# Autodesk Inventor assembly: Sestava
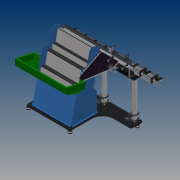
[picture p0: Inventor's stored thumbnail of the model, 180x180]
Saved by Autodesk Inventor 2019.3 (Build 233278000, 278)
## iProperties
Created: 2019-02
Part Number: Sestava
Material: Všeobecné
Document SubType Name: Assembly
Designer: B-hon
Mass: 359871 g
Surface Area: 168702 cm^2
Volume: 49988.6 cm^3
Density: 7.19907 g/cm^3
Stock Number: 19-A0-S-23
Author: B-hon
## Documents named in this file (99)
- C:\Users\B-hon\OneDrive\Plocha\Bakalářka22\Sestava.iam
- C:\Users\B-hon\OneDrive\Plocha\Bakalářka22\Rám\Rám.iam
- C:\Users\B-hon\OneDrive\Plocha\Bakalářka22\Vodící lišta.ipt
- C:\Users\B-hon\OneDrive\Plocha\Bakalářka22\Vozík.ipt
- C:\Users\B-hon\OneDrive\Plocha\Bakalářka22\Výztuha rohu-P.ipt
- C:\Users\B-hon\OneDrive\Plocha\Bakalářka22\Výztuha rohu-L.ipt
- C:\Users\B-hon\OneDrive\Plocha\Bakalářka22\Přítlak spodní\Pravý\Přítlak4s.iam
- C:\Users\B-hon\OneDrive\Plocha\Bakalářka22\Přítlak spodní\Levý\Přítlak3s.iam
- C:\Users\B-hon\OneDrive\Plocha\Bakalářka22\Deska horní\Deska1.iam
- C:\Users\B-hon\OneDrive\Plocha\Bakalářka22\Deska pevná\Deska pevná.iam
- C:\Users\B-hon\OneDrive\Plocha\Bakalářka22\Deska dolní\Deska dolní.iam
- C:\Users\B-hon\OneDrive\Plocha\Bakalářka22\Deska dolní\Ramano pravé.iam
- C:\Users\B-hon\OneDrive\Plocha\Bakalářka22\Deska dolní\Ramano levé.iam
- C:\Users\B-hon\OneDrive\Plocha\Bakalářka22\Deska střední\Deska střední.iam
- C:\Users\B-hon\OneDrive\Plocha\Bakalářka22\Deska střední\Držák desky.ipt
- C:\Users\B-hon\OneDrive\Plocha\Bakalářka22\Přítlak\Střední\Přítlak5.iam
- C:\Users\B-hon\OneDrive\Plocha\Bakalářka22\Deska střední\Rameno pravés.iam
- C:\Users\B-hon\OneDrive\Plocha\Bakalářka22\Deska střední\Rameno levés.iam
- C:\Users\B-hon\OneDrive\Plocha\Bakalářka22\Držák převodovky.ipt
- C:\Users\B-hon\OneDrive\Plocha\Bakalářka22\Převodovka.ipt
- C:\Users\B-hon\OneDrive\Plocha\Bakalářka22\Klika\Klika.iam
- C:\Users\B-hon\OneDrive\Documents\Inventor\Content Center Files\R2019\cs-CZ\CSN 02 2930\CSN 02 2930 - 25.ipt
- C:\Users\B-hon\OneDrive\Plocha\Bakalářka22\Ojnice\Ojnice.iam
- C:\Users\B-hon\OneDrive\Documents\Inventor\Content Center Files\R2019\cs-CZ\DIN 988(2)\DIN 988 - 12 x 18 x 1,8.ipt
- C:\Users\B-hon\OneDrive\Plocha\Bakalářka22\Rozpěrná tyčka\Držák dolní.ipt
- C:\Users\B-hon\OneDrive\Plocha\Bakalářka22\Rozpěrná tyčka\Držák horní.ipt
- C:\Users\B-hon\OneDrive\Plocha\Bakalářka22\Rozpěrná tyčka\Tyčka.ipt
- C:\Users\B-hon\OneDrive\Documents\Inventor\Content Center Files\R2019\cs-CZ\CSN EN 24032\ISO 4032 - M10CSN EN.ipt
- C:\Users\B-hon\OneDrive\Documents\Inventor\Content Center Files\R2019\cs-CZ\CSN EN 24034\ISO 4034 - M10CSN EN.ipt
- C:\Users\B-hon\OneDrive\Plocha\Bakalářka22\Motor.ipt
- C:\Users\B-hon\OneDrive\Plocha\Bakalářka22\Základ2.ipt
- C:\Users\B-hon\OneDrive\Plocha\Bakalářka22\Boční plech.ipt
- C:\Users\B-hon\OneDrive\Plocha\Bakalářka22\Boční plech2.ipt
- C:\Users\B-hon\OneDrive\Plocha\Bakalářka22\Plech přední.ipt
- C:\Users\B-hon\OneDrive\Plocha\Bakalářka22\Plech násypky3.ipt
- C:\Users\B-hon\OneDrive\Plocha\Bakalářka22\Plech násypky1.ipt
- C:\Users\B-hon\OneDrive\Plocha\Bakalářka22\Plech násypky2.ipt
- C:\Users\B-hon\OneDrive\Plocha\Bakalářka22\Plech násypky2-L.ipt
- C:\Users\B-hon\OneDrive\Plocha\Bakalářka22\Plech násypky3-L.ipt
- C:\Users\B-hon\OneDrive\Plocha\Bakalářka22\Plech zadní.ipt
- C:\Users\B-hon\OneDrive\Plocha\Bakalářka22\Držák sloupu.iam
- C:\Users\B-hon\OneDrive\Plocha\Bakalářka22\Úchyt sloupu2.ipt
- C:\Users\B-hon\OneDrive\Plocha\Bakalářka22\Přítlak\Pravý\Přítlak1h.iam
- C:\Users\B-hon\OneDrive\Plocha\Bakalářka22\Přítlak\Levý\Přítlak2h.iam
- C:\Users\B-hon\OneDrive\Plocha\Bakalářka22\Vibrační dopravník3\Dopravník vibrační3.iam
- C:\Users\B-hon\OneDrive\Plocha\Bakalářka22\Skluzová dráha2.ipt
- C:\Users\B-hon\OneDrive\Plocha\Bakalářka22\Držák dráhy.iam
- C:\Users\B-hon\OneDrive\Plocha\Bakalářka22\Držák dráhy2.iam
- C:\Users\B-hon\OneDrive\Plocha\Bakalářka22\Zadní plech krycí.ipt
- C:\Users\B-hon\OneDrive\Documents\Inventor\Content Center Files\R2019\cs-CZ\CNS 4558\CNS 4558 - M4 x 0,7 x 16.ipt
- C:\Users\B-hon\OneDrive\Documents\Inventor\Content Center Files\R2019\cs-CZ\DIN 125-2  A\DIN 125-2 - B 10,5A.ipt
- C:\Users\B-hon\OneDrive\Documents\Inventor\Content Center Files\R2019\cs-CZ\DIN 933\DIN 933 - M10  x 45.ipt
- C:\Users\B-hon\OneDrive\Plocha\Bakalářka22\Antivibrační noha.ipt
- C:\Users\B-hon\OneDrive\Documents\Inventor\Content Center Files\R2019\cs-CZ\ANSI B18.6.4(280)\ANSI B18.6.4 - 1_4-14 - 0,75(22) BP.ipt
- C:\Users\B-hon\OneDrive\Plocha\Bakalářka22\Matice upínací.ipt
- C:\Users\B-hon\OneDrive\Documents\Inventor\Content Center Files\R2019\cs-CZ\DIN 125-1  A\DIN 125 - A 6,4.ipt
- C:\Users\B-hon\OneDrive\Documents\Inventor\Content Center Files\R2019\cs-CZ\DIN 933\DIN 933 - M6  x 45.ipt
- C:\Users\B-hon\OneDrive\Documents\Inventor\Content Center Files\R2019\cs-CZ\DIN 933\DIN 933 - M6  x 35.ipt
- C:\Users\B-hon\OneDrive\Documents\Inventor\Content Center Files\R2019\cs-CZ\DIN 933\DIN 933 - M6  x 6.ipt
- C:\Users\B-hon\OneDrive\Documents\Inventor\Content Center Files\R2019\cs-CZ\ANSI B18.6.4(324)\ANSI B18.6.4 - 1_4-14 - 0,75(26) BP.ipt
- C:\Users\B-hon\OneDrive\Documents\Inventor\Content Center Files\R2019\cs-CZ\DIN 933\DIN 933 - M6  x 16.ipt
- C:\Users\B-hon\OneDrive\Documents\Inventor\Content Center Files\R2019\cs-CZ\CSN EN 24034\ISO 4034 - M6CSN EN.ipt
- C:\Users\B-hon\OneDrive\Documents\Inventor\Content Center Files\R2019\cs-CZ\DIN 7991(2)\DIN 7991 - M4x10.ipt
- C:\Users\B-hon\OneDrive\Plocha\Bakalářka22\Vibrační dopravník3\Základová deska3.ipt
- C:\Users\B-hon\OneDrive\Plocha\Bakalářka22\Příruba.ipt
- C:\Users\B-hon\OneDrive\Plocha\Bakalářka22\Nosný sloup.ipt
- C:\Users\B-hon\OneDrive\Plocha\Bakalářka22\Držák tyče.ipt
- C:\Users\B-hon\OneDrive\Plocha\Bakalářka22\Elektromagnet.ipt
- C:\Users\B-hon\OneDrive\Plocha\Bakalářka22\Tyčka elektromotoru.ipt
- C:\Users\B-hon\OneDrive\Plocha\Bakalářka22\Tyč válce.ipt
- C:\Users\B-hon\OneDrive\Plocha\Bakalářka22\Držák elektromagnetu.ipt
- C:\Users\B-hon\OneDrive\Plocha\Bakalářka22\Zarážka.ipt
- C:\Users\B-hon\OneDrive\Plocha\Bakalářka22\Držák elektromagnetu2.ipt
- C:\Users\B-hon\OneDrive\Documents\Inventor\Content Center Files\R2019\cs-CZ\DIN 933\DIN 933 - M6  x 25.ipt
- C:\Users\B-hon\OneDrive\Documents\Inventor\Content Center Files\R2019\cs-CZ\CNS 4558\CNS 4558 - M6 x 1 x 8.ipt
- C:\Users\B-hon\OneDrive\Documents\Inventor\Content Center Files\R2019\cs-CZ\DIN 125-1  A\DIN 125 - A 4,3.ipt
- C:\Users\B-hon\OneDrive\Documents\Inventor\Content Center Files\R2019\cs-CZ\DIN 933\DIN 933 - M4  x 5.ipt
- C:\Users\B-hon\OneDrive\Plocha\Bakalářka22\Senzor.ipt
- C:\Users\B-hon\OneDrive\Plocha\Bakalářka22\Držák senzoru2.ipt
- C:\Users\B-hon\OneDrive\Plocha\Bakalářka22\Držák senzoru3.ipt
- C:\Users\B-hon\OneDrive\Documents\Inventor\Content Center Files\R2019\cs-CZ\DIN 933\DIN 933 - M6  x 20.ipt
- C:\Users\B-hon\OneDrive\Documents\Inventor\Content Center Files\R2019\cs-CZ\ISO 4035(1)\ISO 4035 - M18DIN EN.ipt
- C:\Users\B-hon\OneDrive\Documents\Inventor\Content Center Files\R2019\cs-CZ\DIN 125-1  A\DIN 125 - A 10,5.ipt
- C:\Users\B-hon\OneDrive\Documents\Inventor\Content Center Files\R2019\cs-CZ\CNS 3932\CNS 3932 - M 6 x 1 x 10.ipt
- C:\Users\B-hon\OneDrive\Documents\Inventor\Content Center Files\R2019\cs-CZ\DIN 933\DIN 933 - M10  x 8.ipt
- C:\Users\B-hon\OneDrive\Documents\Inventor\Content Center Files\R2019\cs-CZ\DIN 125-1  A\DIN 125 - A 15.ipt
- C:\Users\B-hon\OneDrive\Documents\Inventor\Content Center Files\R2019\cs-CZ\CSN EN 24034\ISO 4034 - M14CSN EN.ipt
- C:\Users\B-hon\OneDrive\Documents\Inventor\Content Center Files\R2019\cs-CZ\DIN 933\DIN 933 - M14  x 35.ipt
- C:\Users\B-hon\OneDrive\Documents\Inventor\Content Center Files\R2019\cs-CZ\CSN EN 24034\ISO 4034 - M5CSN EN.ipt
- C:\Users\B-hon\OneDrive\Documents\Inventor\Content Center Files\R2019\cs-CZ\CNS 4558\CNS 4558 - M4 x 0,7 x 10.ipt
- C:\Users\B-hon\OneDrive\Documents\Inventor\Content Center Files\R2019\cs-CZ\DIN 125-1  A\DIN 125 - A 8,4.ipt
- C:\Users\B-hon\OneDrive\Documents\Inventor\Content Center Files\R2019\cs-CZ\CSN EN 24034\ISO 4034 - M8CSN EN.ipt
- C:\Users\B-hon\OneDrive\Documents\Inventor\Content Center Files\R2019\cs-CZ\DIN 933\DIN 933 - M8  x 25.ipt
- C:\Users\B-hon\OneDrive\Documents\Inventor\Content Center Files\R2019\cs-CZ\DIN 933\DIN 933 - M8  x 8.ipt
- C:\Users\B-hon\OneDrive\Documents\Inventor\Content Center Files\R2019\cs-CZ\CNS 4558\CNS 4558 - M4 x 0,7 x 8.ipt
- C:\Users\B-hon\OneDrive\Documents\Inventor\Content Center Files\R2019\cs-CZ\IFI 502(29)\IFI 502 - 6.3x1.8 x 13(4) B.ipt
- C:\Users\B-hon\OneDrive\Plocha\Bakalářka22\Zátka sloupu.ipt
- C:\Users\B-hon\OneDrive\Documents\Inventor\Content Center Files\R2019\cs-CZ\DIN 933\DIN 933 - M12  x 30.ipt
- C:\Users\B-hon\OneDrive\Documents\Inventor\Content Center Files\R2019\cs-CZ\CSN 02 1143  A\CSN 02 1143 - M6 x 1 x 10(1).ipt
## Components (426 placed, 98 different names)
1. Rám:1 [sub-assembly] — Vložit:3, Vložit:4, Vložit:5, Vložit:6, Proti sobě:12, Stejný směr:12, Proti sobě:13, Stejný směr:13, Stejný směr:15, Vložit:76, Vložit:77, Vložit:78, Vložit:79, Proti sobě:26, Stejný směr:19, Proti sobě:29, Stejný směr:20, Proti sobě:67
2. Výztuha rohu-P:1 — Vložit:3, Vložit:4, Stejný směr:18, Proti sobě:286
3. Výztuha rohu-L:1 — Vložit:5, Vložit:6, Proti sobě:23
4. Držák desky:1 — Proti sobě:12, Stejný směr:12, Stejný směr:14, Vložit:90, Vložit:91
5. Držák desky:2 — Proti sobě:13, Stejný směr:13, Stejný směr:14, Stejný směr:15, Vložit:92, Vložit:93
6. Rameno pravés:1 [sub-assembly] — Vložit:65, Vložit:84, Vložit:85, Vložit:86
7. Rameno levés:1 [sub-assembly] — Vložit:64, Vložit:87, Vložit:88, Vložit:89
8. Držák převodovky:1 — Vložit:38, Vložit:39, Proti sobě:24, Stejný směr:18
9. Převodovka:1 — Vložit:38, Vložit:39, Vložit:40, Vložit:60, Vložit:61
10. Klika:1 [sub-assembly] — Vložit:40, Vložit:41, Vložit:42, Vložit:46
11. CSN 02 2930 25:1 — Vložit:41
12. CSN 02 2930 25:2 — Vložit:42
13. Ojnice:1 [sub-assembly] — Vložit:47, Proti sobě:25, Vložit:80
14. DIN 988 12 x 18 x 1,8:1 — Vložit:44, Vložit:45
15. DIN 988 12 x 18 x 1,8:2 — Vložit:44, Vložit:47
16. DIN 988 12 x 18 x 1,8:3 — Vložit:45, Vložit:46
17. Držák dolní:1 — Vložit:52, Proti sobě:16, Vložit:110, Vložit:111
18. Držák horní:1 — Vložit:117, Vložit:118
19. Tyčka:1 — Vložit:52
20. CSN EN 24032 M10:1
21. CSN EN 24032 M10:2 — Proti sobě:16
22. CSN EN 24032 M10:3
23. Držák dolní:2 — Vložit:57, Proti sobě:18, Vložit:112, Vložit:113
24. Tyčka:2 — Vložit:57
25. CSN EN 24034 M10:1 — Proti sobě:18
26. CSN EN 24034 M10:2 — Vložit:124
27. CSN EN 24034 M10:3 — Vložit:125
28. Motor:1 — Vložit:60, Vložit:61
29. Základ2:1 — Proti sobě:23, Proti sobě:24, Proti sobě:30, Proti sobě:37, Proti sobě:41, Úhel:1, Stejný směr:33, Stejný směr:34, Úhel:2, Úhel:3, Vložit:142, Vložit:143, Vložit:144, Vložit:145, Stejný směr:42, Úhel:22, Proti sobě:230, Proti sobě:232, Proti sobě:234, Proti sobě:236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
30. Deska dolní:1 [sub-assembly] — Stejný směr:17, Proti sobě:35, Stejný směr:35, Vložit:102, Vložit:103, Vložit:108, Vložit:109
31. Deska střední:1 [sub-assembly] — Vložit:64, Vložit:65, Vložit:86, Vložit:89, Stejný směr:35, Úhel:12
32. Držák horní:3 — Vložit:122, Vložit:123, Vložit:124, Vložit:125
33. Deska pevná:1 [sub-assembly] — Vložit:78, Vložit:79, Stejný směr:36, Proti sobě:50, Proti sobě:51, Proti sobě:68
34. Boční plech:1 — Proti sobě:26, Stejný směr:19, Proti sobě:32, Stejný směr:22, Proti sobě:34, Stejný směr:39, Proti sobě:89, Proti sobě:139, Proti sobě:141, Proti sobě:163
35. Boční plech2:1 — Proti sobě:29, Stejný směr:20, Proti sobě:31, Stejný směr:21, Proti sobě:36, Stejný směr:28, Proti sobě:38, Stejný směr:32, Stejný směr:33, Stejný směr:41, Vložit:221, Proti sobě:266
36. Plech přední:1 — Proti sobě:30, Proti sobě:31, Stejný směr:21, Proti sobě:33, Stejný směr:34
37. Plech násypky3:1 — Proti sobě:32, Stejný směr:22, Stejný směr:23, Proti sobě:63, Proti sobě:167
38. Plech násypky1:1 — Proti sobě:33, Stejný směr:23, Proti sobě:34, Proti sobě:35, Stejný směr:24, Stejný směr:25, Stejný směr:26, Stejný směr:27, Stejný směr:29, Stejný směr:30, Stejný směr:31
39. Plech násypky2:1 — Stejný směr:24, Stejný směr:25, Stejný směr:26
40. Plech násypky2-L:1 — Stejný směr:27, Stejný směr:30, Stejný směr:31
41. Plech násypky3-L:1 — Proti sobě:36, Stejný směr:28, Stejný směr:29, Proti sobě:165
42. Plech zadní:1 — Proti sobě:37, Proti sobě:38, Stejný směr:32
43. Přítlak5:1 [sub-assembly] — Vložit:84, Vložit:85, Vložit:90, Vložit:91
44. Přítlak5:2 [sub-assembly] — Vložit:87, Vložit:88, Vložit:92, Vložit:93
45. Přítlak4s:1 [sub-assembly] — Vložit:104, Vložit:105, Vložit:106, Vložit:107, Vložit:110, Vložit:111
46. Přítlak3s:1 [sub-assembly] — Vložit:96, Vložit:97, Vložit:100, Vložit:101, Vložit:112, Vložit:113
47. Ramano levé:1 [sub-assembly] — Vložit:104, Vložit:105, Vložit:108, Vložit:109
48. Ramano pravé:1 [sub-assembly] — Vložit:96, Vložit:97, Vložit:102, Vložit:103
49. Přítlak1h:1 [sub-assembly] — Vložit:114, Vložit:115, Proti sobě:47, Vložit:117, Vložit:118
50. Přítlak2h:1 [sub-assembly] — Vložit:119, Proti sobě:48, Vložit:122, Vložit:123, Vložit:180
51. Dopravník vibrační3:1 [sub-assembly] — Úhel:2, Úhel:3, Stejný směr:36, Proti sobě:50, Proti sobě:51, Proti sobě:62, Proti sobě:88, Proti sobě:146, Proti sobě:147, Proti sobě:148, Proti sobě:149, Stejný směr:40, Proti sobě:150, Proti sobě:151, Proti sobě:152, Proti sobě:153, Proti sobě:155, Proti sobě:157, Proti sobě:159, Proti sobě:161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
52. Skluzová dráha2:1 — Proti sobě:62, Proti sobě:63, Proti sobě:64, Proti sobě:88, Proti sobě:89, Vložit:133, Vložit:134, Vložit:138, Vložit:139
53. Držák dráhy:1 [sub-assembly] — Proti sobě:64, Vložit:128, Vložit:133, Vložit:134, Proti sobě:272, Proti sobě:274, Proti sobě:276, Proti sobě:278
54. Držák dráhy2:1 [sub-assembly] — Vložit:128, Proti sobě:182
55. CNS 4558 M4 x 16:1 — Vložit:138
56. CNS 4558 M4 x 16:2 — Vložit:139
57. Antivibrační noha:1 — Proti sobě:129
58. Antivibrační noha:2 — Proti sobě:125
59. Antivibrační noha:3 — Proti sobě:127
60. Antivibrační noha:4 — Proti sobě:123
61. CSN EN 24034 M10:4 — Proti sobě:123, Proti sobě:131
62. CSN EN 24034 M10:5 — Proti sobě:125, Proti sobě:133
63. CSN EN 24034 M10:6 — Proti sobě:127, Proti sobě:135
64. CSN EN 24034 M10:7 — Proti sobě:129, Proti sobě:137
65. DIN 125-2 A B 10,5:17 — Proti sobě:131, Vložit:143
66. DIN 125-2 A B 10,5:18 — Proti sobě:133, Vložit:144
67. DIN 125-2 A B 10,5:19 — Proti sobě:135, Vložit:145
68. DIN 125-2 A B 10,5:20 — Proti sobě:137, Vložit:142
69. DIN 125-1 A A 6,4:1 — Proti sobě:155, Vložit:154
70. DIN 125-1 A A 6,4:2 — Proti sobě:157
71. Deska1:1 [sub-assembly] — Stejný směr:17, Proti sobě:25, Vložit:80, Proti sobě:47, Vložit:180, Úhel:12
72. Zadní plech krycí:1 — Proti sobě:67, Stejný směr:39, Proti sobě:68
73. CSN EN 24034 M6:1 — Proti sobě:169
74. CSN EN 24034 M6:2 — Proti sobě:171
75. CSN EN 24034 M6:3 — Proti sobě:173
76. CSN EN 24034 M6:4 — Proti sobě:175
77. Šroub do plechu s vroubkovanou šestihrannou hlavou s drážkou a podložkou - Typ BP - Palcový 1/4-14 - 0,75:7
78. Šroub do plechu s vroubkovanou šestihrannou hlavou s drážkou a podložkou - Typ BP - Palcový 1/4-14 - 0,75:8
79. Šroub do plechu s vroubkovanou šestihrannou hlavou s drážkou a podložkou - Typ BP - Palcový 1/4-14 - 0,75:9
80. DIN 933 - nahrazený DIN EN 24017 M6  x 6:4
81. DIN 933 - nahrazený DIN EN 24017 M6  x 6:5
82. DIN 933 - nahrazený DIN EN 24017 M6  x 6:6
83. Základová deska3:1 — Vložit:181, Vložit:183, Vložit:184, Úhel:13, Proti sobě:187, Úhel:22, Proti sobě:218, Proti sobě:223, Proti sobě:224
84. Držák tyče:1 — Proti sobě:182, Úhel:13, Proti sobě:189, Proti sobě:224, Proti sobě:260
85. Elektromagnet:1 — Úhel:15, Proti sobě:195, Úhel:16, Vložit:188, Proti sobě:197
86. Tyčka elektromotoru:1 — Vložit:187, Proti sobě:197
87. Držák tyče:2 — Proti sobě:187, Proti sobě:189, Proti sobě:190, Stejný směr:46, Stejný směr:47, Proti sobě:223, Proti sobě:262
88. Tyč válce:1 — Proti sobě:190, Proti sobě:191, Proti sobě:192, Proti sobě:193
89. Držák elektromagnetu:1 — Proti sobě:191, Proti sobě:192, Proti sobě:193, Úhel:14, Proti sobě:194, Úhel:16, Proti sobě:196, Proti sobě:205, Proti sobě:207, Stejný směr:45
90. Zarážka:1 — Vložit:187, Úhel:15, Proti sobě:199
91. Držák elektromagnetu2:1 — Vložit:188, Proti sobě:196, Proti sobě:202, Proti sobě:203, Stejný směr:45, Úhel:21, Proti sobě:217, Vložit:200, Vložit:203, Vložit:204
92. DIN 125-1 A A 6,4:31 — Proti sobě:199, Proti sobě:201
93. CSN EN 24034 M6:5 — Proti sobě:201
94. DIN 125-1 A A 6,4:32 — Proti sobě:202, Vložit:192
95. DIN 125-1 A A 6,4:33 — Proti sobě:203, Vložit:191
96. DIN 125-1 A A 6,4:34 — Proti sobě:205
97. DIN 125-1 A A 6,4:35 — Proti sobě:207
98. CSN EN 24034 M6:6 — Proti sobě:208
99. CSN EN 24034 M6:7 — Proti sobě:209
100. DIN 933 - nahrazený DIN EN 24017 M6  x 25:1 — Vložit:192, Proti sobě:208
101. DIN 933 - nahrazený DIN EN 24017 M6  x 25:2 — Vložit:191, Proti sobě:209
102. DIN 933 - nahrazený DIN EN 24017 M4  x 5:1
103. DIN 933 - nahrazený DIN EN 24017 M4  x 5:2
104. DIN 933 - nahrazený DIN EN 24017 M4  x 5:3
105. Držák tyče:3 — Proti sobě:218, Stejný směr:46, Stejný směr:47, Proti sobě:219, Proti sobě:264, Proti sobě:284
106. Tyč válce:2 — Proti sobě:219, Proti sobě:220, Proti sobě:221
107. Držák senzoru3:1 — Proti sobě:220, Proti sobě:221, Proti sobě:222, Vložit:201, Vložit:210, Vložit:211
108. DIN 125-1 A A 6,4:37 — Vložit:202, Vložit:207
109. DIN 125-1 A A 6,4:38 — Proti sobě:225, Vložit:208
110. DIN 125-1 A A 6,4:39 — Vložit:203, Vložit:206
111. DIN 125-1 A A 6,4:40 — Vložit:204, Vložit:205
112. CSN EN 24034 M6:8 — Vložit:206
113. CSN EN 24034 M6:9 — Vložit:205, Proti sobě:226
114. DIN 933 - nahrazený DIN EN 24017 M6  x 20:1 — Vložit:207
115. DIN 933 - nahrazený DIN EN 24017 M6  x 20:2 — Vložit:208, Proti sobě:226
116. DIN 933 - nahrazený DIN EN 24017 M6  x 25:3 — Vložit:215, Proti sobě:228
117. DIN 933 - nahrazený DIN EN 24017 M6  x 25:4 — Vložit:214
118. CSN EN 24034 M6:10 — Vložit:213, Proti sobě:228
119. CSN EN 24034 M6:11 — Vložit:212
120. DIN 125-1 A A 6,4:41 — Proti sobě:227, Vložit:215
121. DIN 125-1 A A 6,4:42 — Vložit:211, Vložit:213
122. DIN 125-1 A A 6,4:43 — Vložit:210, Vložit:212
123. DIN 125-1 A A 6,4:44 — Vložit:209, Vložit:214
124. DIN 125-1 A A 10,5:1 — Proti sobě:230
125. DIN 125-1 A A 10,5:2 — Proti sobě:232
126. DIN 125-1 A A 10,5:3 — Proti sobě:234
127. DIN 125-1 A A 10,5:4 — Proti sobě:236
128. DIN 125-1 A A 10,5:5 — Proti sobě:238
129. DIN 125-1 A A 10,5:6 — Proti sobě:240
130. DIN 125-1 A A 10,5:7 — Proti sobě:242
131. DIN 125-1 A A 10,5:8 — Proti sobě:244
132. DIN 125-1 A A 10,5:9 — Proti sobě:246, Proti sobě:254
133. DIN 125-1 A A 10,5:10 — Proti sobě:248
134. DIN 125-1 A A 10,5:11 — Proti sobě:250, Proti sobě:256
135. DIN 125-1 A A 10,5:12 — Proti sobě:252, Proti sobě:258
136. CNS 3932 M 6 x 10:1 — Proti sobě:260
137. CNS 3932 M 6 x 10:2 — Proti sobě:262
138. CNS 3932 M 6 x 10:3 — Proti sobě:264
139. DIN 125-1 A A 15:1 — Proti sobě:272, Vložit:223
140. DIN 125-1 A A 15:2 — Proti sobě:274, Vložit:222
141. CSN EN 24034 M14:1 — Vložit:222
142. DIN 933 - nahrazený DIN EN 24017 M14  x 35:1 — Vložit:223
143. DIN 125-1 A A 4,3:4 — Proti sobě:276, Proti sobě:282
144. DIN 125-1 A A 4,3:5 — Proti sobě:278, Proti sobě:280
145. CSN EN 24034 M5:1 — Proti sobě:280
146. CSN EN 24034 M5:2 — Proti sobě:282
147. DIN 125-1 A A 6,4:45
148. DIN 125-1 A A 6,4:46
149. DIN 125-1 A A 6,4:47
150. DIN 125-1 A A 6,4:48
151. DIN 125-1 A A 6,4:49
152. DIN 125-1 A A 6,4:50 — Proti sobě:284
153. DIN 933 - nahrazený DIN EN 24017 M6  x 6:8
154. DIN 933 - nahrazený DIN EN 24017 M6  x 6:9
155. DIN 933 - nahrazený DIN EN 24017 M6  x 6:10
156. DIN 933 - nahrazený DIN EN 24017 M6  x 6:11
157. DIN 933 - nahrazený DIN EN 24017 M6  x 6:12
158. DIN 933 - nahrazený DIN EN 24017 M6  x 6:13
159. DIN 125-1 A A 8,4:1
160. DIN 125-1 A A 8,4:2
161. DIN 125-1 A A 8,4:3
162. DIN 125-1 A A 8,4:4
163. DIN 125-1 A A 8,4:5
164. DIN 125-1 A A 8,4:6 — Proti sobě:286
165. DIN 125-1 A A 8,4:7 — Vložit:251
166. DIN 125-1 A A 8,4:8 — Vložit:252
167. DIN 125-1 A A 8,4:9
168. DIN 125-1 A A 8,4:10
169. DIN 125-1 A A 8,4:11
170. DIN 125-1 A A 8,4:12
171. CSN EN 24034 M8:1
172. CSN EN 24034 M8:2
173. CSN EN 24034 M8:3
174. CSN EN 24034 M8:4
175. DIN 933 - nahrazený DIN EN 24017 M8  x 25:1 — Vložit:251
176. DIN 933 - nahrazený DIN EN 24017 M8  x 25:2 — Vložit:252
177. DIN 933 - nahrazený DIN EN 24017 M8  x 8:1
178. DIN 933 - nahrazený DIN EN 24017 M8  x 8:2
179. DIN 933 - nahrazený DIN EN 24017 M8  x 8:3
180. DIN 933 - nahrazený DIN EN 24017 M8  x 8:4
181. DIN 933 - nahrazený DIN EN 24017 M8  x 8:5
182. DIN 933 - nahrazený DIN EN 24017 M8  x 8:6
183. CNS 4558 M4 x 8:1
184. CSN 02 1143 A M6 x 10:1
185. CSN 02 1143 A M6 x 10:2
186. CSN 02 1143 A M6 x 10:3
187. CSN 02 1143 A M6 x 10:4
188. DIN 125-1 A A 6,4:54
189. DIN 125-1 A A 6,4:55
190. DIN 125-1 A A 6,4:56 — Proti sobě:293
191. DIN 933 - nahrazený DIN EN 24017 M6  x 6:15
192. DIN 933 - nahrazený DIN EN 24017 M6  x 6:16 — Proti sobě:293
193. DIN 933 - nahrazený DIN EN 24017 M6  x 6:17
194. Vozík:1 — Proti sobě:2, Proti sobě:3, Vložit:106, Vložit:107
195. Vozík:2 — Vložit:100, Vložit:101
196. Vozík:3 — Proti sobě:5, Proti sobě:6, Vložit:114, Vložit:115
197. Vozík:4 — Vložit:119, Proti sobě:48
198. Vodící lišta:1 — Proti sobě:2, Proti sobě:3, Proti sobě:5, Proti sobě:6, Vložit:76, Vložit:77
199. Vodící lišta:2
200. Šroub do plechu s vroubkovanou šestihrannou hlavou s drážkou a podložkou - Typ BP - Palcový 1/4-14 - 0,75:1 — Proti sobě:139
201. Šroub do plechu s vroubkovanou šestihrannou hlavou s drážkou a podložkou - Typ BP - Palcový 1/4-14 - 0,75:2
202. Šroub do plechu s vroubkovanou šestihrannou hlavou s drážkou a podložkou - Typ BP - Palcový 1/4-14 - 0,75:3
203. Šroub do plechu s vroubkovanou šestihrannou hlavou s drážkou a podložkou - Typ BP - Palcový 1/4-14 - 0,75:4 — Proti sobě:141
204. Šroub do plechu s vroubkovanou šestihrannou hlavou s drážkou a podložkou - Typ BP - Palcový 1/4-14 - 0,75:5
205. Šroub do plechu s vroubkovanou šestihrannou hlavou s drážkou a podložkou - Typ BP - Palcový 1/4-14 - 0,75:6
206. Matice upínací:1 — Proti sobě:146, Proti sobě:147, Stejný směr:40
207. Matice upínací:3
208. Matice upínací:4
209. Matice upínací:5
210. Matice upínací:2 — Proti sobě:148, Proti sobě:149, Proti sobě:150
211. Matice upínací:6
212. Matice upínací:7
213. Matice upínací:8
214. Matice upínací:9
215. Matice upínací:10
216. Matice upínací:11
217. Matice upínací:12
218. Matice upínací:13 — Proti sobě:151, Proti sobě:152, Proti sobě:153
219. Matice upínací:14
220. Matice upínací:15
221. Matice upínací:16
222. DIN 933 - nahrazený DIN EN 24017 M6  x 35:3 — Vložit:154
223. DIN 933 - nahrazený DIN EN 24017 M6  x 35:4
224. DIN 933 - nahrazený DIN EN 24017 M6  x 45:2 — Vložit:153
225. DIN 125-1 A A 6,4:5 — Proti sobě:161, Vložit:153
226. DIN 933 - nahrazený DIN EN 24017 M6  x 35:1 — Vložit:156
227. DIN 125-1 A A 6,4:6 — Vložit:156
228. DIN 933 - nahrazený DIN EN 24017 M6  x 45:4
229. DIN 125-1 A A 6,4:9
230. DIN 933 - nahrazený DIN EN 24017 M6  x 35:6
231. DIN 125-1 A A 6,4:10
232. DIN 933 - nahrazený DIN EN 24017 M6  x 45:5
233. DIN 125-1 A A 6,4:11
234. DIN 933 - nahrazený DIN EN 24017 M6  x 35:7
235. DIN 125-1 A A 6,4:12
236. DIN 933 - nahrazený DIN EN 24017 M6  x 45:6
237. DIN 125-1 A A 6,4:13
238. DIN 933 - nahrazený DIN EN 24017 M6  x 35:8
239. DIN 125-1 A A 6,4:14
240. DIN 125-1 A A 6,4:15
241. DIN 125-1 A A 6,4:16
242. DIN 125-1 A A 6,4:17
243. DIN 933 - nahrazený DIN EN 24017 M6  x 6:1
244. DIN 933 - nahrazený DIN EN 24017 M6  x 6:2
245. DIN 933 - nahrazený DIN EN 24017 M6  x 6:3
246. Šroub do plechu s normální vroubkovanou šestihrannou hlavou - Typ BP - Palcový 1/4-14 - 0,75:1 — Proti sobě:163
247. Šroub do plechu s normální vroubkovanou šestihrannou hlavou - Typ BP - Palcový 1/4-14 - 0,75:2
248. DIN 125-1 A A 6,4:18 — Proti sobě:165, Vložit:162
249. DIN 125-1 A A 6,4:19
250. DIN 125-1 A A 6,4:20 — Proti sobě:167
251. DIN 125-1 A A 6,4:21
252. DIN 125-1 A A 6,4:22 — Proti sobě:173
253. DIN 125-1 A A 6,4:23 — Proti sobě:175
254. DIN 125-1 A A 6,4:24 — Proti sobě:169
255. DIN 125-1 A A 6,4:25 — Proti sobě:171
256. DIN 933 - nahrazený DIN EN 24017 M6  x 16:1 — Vložit:162
257. DIN 933 - nahrazený DIN EN 24017 M6  x 16:2
258. DIN 933 - nahrazený DIN EN 24017 M6  x 16:3
259. DIN 933 - nahrazený DIN EN 24017 M6  x 16:4
260. Šroub do plechu s vroubkovanou šestihrannou hlavou s drážkou a podložkou - Typ BP - Palcový 1/4-14 - 0,75:13
261. Šroub do plechu s vroubkovanou šestihrannou hlavou s drážkou a podložkou - Typ BP - Palcový 1/4-14 - 0,75:14
262. Šroub do plechu s vroubkovanou šestihrannou hlavou s drážkou a podložkou - Typ BP - Palcový 1/4-14 - 0,75:15
263. Šroub do plechu s vroubkovanou šestihrannou hlavou s drážkou a podložkou - Typ BP - Palcový 1/4-14 - 0,75:16
264. Šroub do plechu s vroubkovanou šestihrannou hlavou s drážkou a podložkou - Typ BP - Palcový 1/4-14 - 0,75:17
265. Šroub do plechu s vroubkovanou šestihrannou hlavou s drážkou a podložkou - Typ BP - Palcový 1/4-14 - 0,75:18
266. DIN 125-1 A A 6,4:26
267. DIN 125-1 A A 6,4:27
268. DIN 125-1 A A 6,4:28
269. DIN 933 - nahrazený DIN EN 24017 M6  x 45:1 — Vložit:152
270. DIN 125-1 A A 6,4:4 — Vložit:152
271. DIN 933 - nahrazený DIN EN 24017 M6  x 35:2 — Vložit:155
272. DIN 125-1 A A 6,4:3 — Proti sobě:159, Vložit:155
273. DIN 933 - nahrazený DIN EN 24017 M6  x 45:7
274. DIN 125-1 A A 6,4:29
275. DIN 933 - nahrazený DIN EN 24017 M6  x 35:9
276. DIN 125-1 A A 6,4:30
277. DIN 933 - nahrazený DIN EN 24017 M6  x 45:8
278. DIN 125-1 A A 6,4:51
279. DIN 933 - nahrazený DIN EN 24017 M6  x 35:10
280. DIN 125-1 A A 6,4:52
281. DIN 7991 M4x10:1 — Vložit:176
282. DIN 7991 M4x10:3
283. DIN 7991 M4x10:4
284. Držák sloupu:1 [sub-assembly] — Proti sobě:41, Úhel:1, Proti sobě:46, Proti sobě:91, Proti sobě:93, Proti sobě:95, Proti sobě:97, Stejný směr:42, Proti sobě:180, Stejný směr:44, Proti sobě:291
285. DIN 125-2 A B 10,5:7 — Proti sobě:103, Vložit:140
286. DIN 125-2 A B 10,5:5 — Proti sobě:99
287. DIN 125-2 A B 10,5:8 — Proti sobě:105
288. DIN 125-2 A B 10,5:6 — Proti sobě:101
289. DIN 125-2 A B 10,5:2 — Proti sobě:93
290. DIN 125-2 A B 10,5:3 — Proti sobě:95
291. DIN 125-2 A B 10,5:4 — Proti sobě:97
292. DIN 125-2 A B 10,5:1 — Proti sobě:91, Vložit:141
293. Držák sloupu:2 [sub-assembly]
294. DIN 125-2 A B 10,5:21
295. DIN 125-2 A B 10,5:22
296. DIN 125-2 A B 10,5:23
297. DIN 125-2 A B 10,5:24
298. DIN 125-2 A B 10,5:25
299. DIN 125-2 A B 10,5:26
300. DIN 125-2 A B 10,5:27
301. DIN 125-2 A B 10,5:28
302. Držák sloupu:3 [sub-assembly]
303. DIN 125-2 A B 10,5:29
304. DIN 125-2 A B 10,5:30
305. DIN 125-2 A B 10,5:31
306. DIN 125-2 A B 10,5:32
307. DIN 125-2 A B 10,5:33
308. DIN 125-2 A B 10,5:34
309. DIN 125-2 A B 10,5:35
310. DIN 125-2 A B 10,5:36
311. Příruba:1 — Vložit:183, Vložit:184, Vložit:185, Proti sobě:268
312. Příruba:2
313. Příruba:3
314. CNS 4558 M6 x 8:1
315. CNS 4558 M6 x 8:2
316. DIN 125-1 A A 4,3:1
317. DIN 125-1 A A 4,3:2
318. DIN 125-1 A A 4,3:3
319. Senzor:2 — Vložit:199
320. Senzor:1 — Vložit:198
321. Držák senzoru2:1 — Úhel:21, Vložit:198, Vložit:199, Proti sobě:217, Vložit:200, Vložit:202, Proti sobě:225, Vložit:216, Vložit:217, Vložit:218, Vložit:219
322. Senzor:3
323. Senzor:4
324. Držák senzoru2:2 — Proti sobě:222, Vložit:201, Vložit:209, Proti sobě:227
325. DIN EN 24035 M18:4 — Vložit:218
326. DIN EN 24035 M18:3 — Vložit:219
327. DIN EN 24035 M18:2 — Vložit:217
328. DIN EN 24035 M18:1 — Vložit:216
329. DIN EN 24035 M18:5
330. DIN EN 24035 M18:6
331. DIN EN 24035 M18:7
332. DIN EN 24035 M18:8
333. Šroub do plechu s vroubkovanou šestihrannou hlavou s drážkou a podložkou - Typ BP - Palcový 1/4-14 - 0,75:10 — Vložit:221
334. Šroub do plechu s vroubkovanou šestihrannou hlavou s drážkou a podložkou - Typ BP - Palcový 1/4-14 - 0,75:25
335. Šroub do plechu s vroubkovanou šestihrannou hlavou s drážkou a podložkou - Typ BP - Palcový 1/4-14 - 0,75:26
336. Šroub do plechu s vroubkovanou šestihrannou hlavou s drážkou a podložkou - Typ BP - Palcový 1/4-14 - 0,75:27 — Proti sobě:266
337. Šroub do plechu s vroubkovanou šestihrannou hlavou s drážkou a podložkou - Typ BP - Palcový 1/4-14 - 0,75:28
338. CSN EN 24034 M10:9
339. CSN EN 24034 M10:8 — Proti sobě:254
340. CSN EN 24034 M10:11 — Proti sobě:258
341. CSN EN 24034 M10:10 — Proti sobě:256
342. CSN EN 24034 M10:12
343. CSN EN 24034 M10:13
344. CSN EN 24034 M10:14
345. CSN EN 24034 M10:15
346. CSN EN 24034 M10:16
347. CSN EN 24034 M10:17
348. CSN EN 24034 M10:18
349. CSN EN 24034 M10:19
350. CNS 4558 M4 x 10:1 — Vložit:235
351. CNS 4558 M4 x 10:2
352. CNS 4558 M4 x 10:3
353. CNS 4558 M4 x 10:4
354. DIN 125-1 A A 6,4:36 — Proti sobě:214, Proti sobě:215, Proti sobě:216
355. DIN 933 - nahrazený DIN EN 24017 M6  x 6:7 — Úhel:19
356. DIN 125-1 A A 6,4:53
357. DIN 933 - nahrazený DIN EN 24017 M6  x 6:14
358. Šroub do plechu s vroubkovanou šestihrannou hlavou s nákružkem - Typ B - Metrický 6.3x1.8 x 13:2
359. Šroub do plechu s vroubkovanou šestihrannou hlavou s nákružkem - Typ B - Metrický 6.3x1.8 x 13:3
360. Šroub do plechu s vroubkovanou šestihrannou hlavou s nákružkem - Typ B - Metrický 6.3x1.8 x 13:4
361. Šroub do plechu s vroubkovanou šestihrannou hlavou s nákružkem - Typ B - Metrický 6.3x1.8 x 13:5
362. Šroub do plechu s vroubkovanou šestihrannou hlavou s nákružkem - Typ B - Metrický 6.3x1.8 x 13:6
363. Šroub do plechu s vroubkovanou šestihrannou hlavou s nákružkem - Typ B - Metrický 6.3x1.8 x 13:7
364. Nosný sloup:1 — Vložit:185, Vložit:261, Proti sobě:291
365. Nosný sloup:2
366. Nosný sloup:3
367. DIN 933 - nahrazený DIN EN 24017 M12  x 30:1 — Proti sobě:289, Proti sobě:290
368. Zátka sloupu:1 — Vložit:261, Proti sobě:289
369. DIN 933 - nahrazený DIN EN 24017 M12  x 30:2
370. Zátka sloupu:2
371. DIN 933 - nahrazený DIN EN 24017 M12  x 30:3
372. Zátka sloupu:3
373. Úchyt sloupu2:1 — Proti sobě:46, Proti sobě:103, Proti sobě:105
374. Úchyt sloupu2:2 — Proti sobě:99, Proti sobě:101, Proti sobě:180, Stejný směr:44
375. DIN 933 - nahrazený DIN EN 24017 M10  x 45:1 — Vložit:140
376. DIN 933 - nahrazený DIN EN 24017 M10  x 45:6
377. DIN 933 - nahrazený DIN EN 24017 M10  x 45:7
378. DIN 933 - nahrazený DIN EN 24017 M10  x 45:8
379. DIN 933 - nahrazený DIN EN 24017 M10  x 45:2 — Vložit:141
380. DIN 933 - nahrazený DIN EN 24017 M10  x 45:3
381. DIN 933 - nahrazený DIN EN 24017 M10  x 45:4
382. DIN 933 - nahrazený DIN EN 24017 M10  x 45:5
383. Úchyt sloupu2:3
384. Úchyt sloupu2:4
385. DIN 933 - nahrazený DIN EN 24017 M10  x 45:9
386. DIN 933 - nahrazený DIN EN 24017 M10  x 45:10
387. DIN 933 - nahrazený DIN EN 24017 M10  x 45:11
388. DIN 933 - nahrazený DIN EN 24017 M10  x 45:12
389. DIN 933 - nahrazený DIN EN 24017 M10  x 45:13
390. DIN 933 - nahrazený DIN EN 24017 M10  x 45:14
391. DIN 933 - nahrazený DIN EN 24017 M10  x 45:15
392. DIN 933 - nahrazený DIN EN 24017 M10  x 45:16
393. Úchyt sloupu2:5
394. Úchyt sloupu2:6
395. DIN 933 - nahrazený DIN EN 24017 M10  x 45:17
396. DIN 933 - nahrazený DIN EN 24017 M10  x 45:18
397. DIN 933 - nahrazený DIN EN 24017 M10  x 45:19
398. DIN 933 - nahrazený DIN EN 24017 M10  x 45:20
399. DIN 933 - nahrazený DIN EN 24017 M10  x 45:21
400. DIN 933 - nahrazený DIN EN 24017 M10  x 45:22
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## Component patterns: Pole komponent 5:2 (2 elements), Pole komponent 14:2 (4 elements), Pole komponent 13:2 (4 elements), Pole komponent 5:3 (2 elements), Pole komponent 14:3 (4 elements), Pole komponent 13:3 (4 elements), Pole komponent 62:2 (4 elements), Pole komponent 61:2 (4 elements), Pole komponent 62:3 (4 elements), Pole komponent 61:3 (4 elements)
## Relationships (298: Mate 140, Insert 115, Flush 32, Angle 11)
- Proti sobě:2 [Mate]: Vozík:1 ↔ Vodící lišta:1
- Proti sobě:3 [Mate]: Vozík:1 ↔ Vodící lišta:1
- Vložit:3 [Insert]: Rám:1 ↔ Výztuha rohu-P:1
- Vložit:4 [Insert]: Rám:1 ↔ Výztuha rohu-P:1
- Vložit:5 [Insert]: Rám:1 ↔ Výztuha rohu-L:1
- Vložit:6 [Insert]: Rám:1 ↔ Výztuha rohu-L:1
- Proti sobě:5 [Mate]: Vozík:3 ↔ Vodící lišta:1
- Proti sobě:6 [Mate]: Vozík:3 ↔ Vodící lišta:1
- Proti sobě:12 [Mate]: Rám:1 ↔ Držák desky:1
- Stejný směr:12 [Flush]: Rám:1 ↔ Držák desky:1
- Proti sobě:13 [Mate]: Rám:1 ↔ Držák desky:2
- Stejný směr:13 [Flush]: Rám:1 ↔ Držák desky:2
- Stejný směr:14 [Flush]: Držák desky:1 ↔ Držák desky:2
- Vložit:38 [Insert]: Držák převodovky:1 ↔ Převodovka:1
- Vložit:39 [Insert]: Držák převodovky:1 ↔ Převodovka:1
- Vložit:40 [Insert]: Převodovka:1 ↔ Klika:1
- Vložit:41 [Insert]: Klika:1 ↔ CSN 02 2930 25:1
- Vložit:42 [Insert]: Klika:1 ↔ CSN 02 2930 25:2
- Vložit:44 [Insert]: DIN 988 12 x 18 x 1,8:1 ↔ DIN 988 12 x 18 x 1,8:2
- Vložit:45 [Insert]: DIN 988 12 x 18 x 1,8:1 ↔ DIN 988 12 x 18 x 1,8:3
- Vložit:46 [Insert]: Klika:1 ↔ DIN 988 12 x 18 x 1,8:3
- Vložit:47 [Insert]: Ojnice:1 ↔ DIN 988 12 x 18 x 1,8:2
- Vložit:52 [Insert]: Držák dolní:1 ↔ Tyčka:1
- Proti sobě:16 [Mate]: Držák dolní:1 ↔ CSN EN 24032 M10:2
- Vložit:57 [Insert]: Držák dolní:2 ↔ Tyčka:2
- Proti sobě:18 [Mate]: Držák dolní:2 ↔ CSN EN 24034 M10:1
- Vložit:60 [Insert]: Převodovka:1 ↔ Motor:1
- Vložit:61 [Insert]: Převodovka:1 ↔ Motor:1
- Vložit:64 [Insert]: Rameno levés:1 ↔ Deska střední:1
- Vložit:65 [Insert]: Rameno pravés:1 ↔ Deska střední:1
- Stejný směr:15 [Flush]: Rám:1 ↔ Držák desky:2
- Proti sobě:23 [Mate]: Výztuha rohu-L:1 ↔ Základ2:1
- Stejný směr:17 [Flush]: Deska dolní:1 ↔ Deska1:1
- Vložit:76 [Insert]: Rám:1 ↔ Vodící lišta:1
- Vložit:77 [Insert]: Rám:1 ↔ Vodící lišta:1
- Vložit:78 [Insert]: Rám:1 ↔ Deska pevná:1
- Vložit:79 [Insert]: Rám:1 ↔ Deska pevná:1
- Proti sobě:24 [Mate]: Držák převodovky:1 ↔ Základ2:1
- Proti sobě:25 [Mate]: Ojnice:1 ↔ Deska1:1
- Vložit:80 [Insert]: Ojnice:1 ↔ Deska1:1
- Stejný směr:18 [Flush]: Výztuha rohu-P:1 ↔ Držák převodovky:1
- Proti sobě:26 [Mate]: Rám:1 ↔ Boční plech:1
- Stejný směr:19 [Flush]: Rám:1 ↔ Boční plech:1
- Proti sobě:29 [Mate]: Rám:1 ↔ Boční plech2:1
- Stejný směr:20 [Flush]: Rám:1 ↔ Boční plech2:1
- Proti sobě:30 [Mate]: Základ2:1 ↔ Plech přední:1
- Proti sobě:31 [Mate]: Boční plech2:1 ↔ Plech přední:1
- Stejný směr:21 [Flush]: Boční plech2:1 ↔ Plech přední:1
- Proti sobě:32 [Mate]: Boční plech:1 ↔ Plech násypky3:1
- Stejný směr:22 [Flush]: Boční plech:1 ↔ Plech násypky3:1
- Proti sobě:33 [Mate]: Plech přední:1 ↔ Plech násypky1:1
- Stejný směr:23 [Flush]: Plech násypky3:1 ↔ Plech násypky1:1
- Proti sobě:34 [Mate]: Boční plech:1 ↔ Plech násypky1:1
- Proti sobě:35 [Mate]: Deska dolní:1 ↔ Plech násypky1:1
- Stejný směr:24 [Flush]: Plech násypky1:1 ↔ Plech násypky2:1
- Stejný směr:25 [Flush]: Plech násypky1:1 ↔ Plech násypky2:1
- Stejný směr:26 [Flush]: Plech násypky1:1 ↔ Plech násypky2:1
- Stejný směr:27 [Flush]: Plech násypky1:1 ↔ Plech násypky2-L:1
- Proti sobě:36 [Mate]: Boční plech2:1 ↔ Plech násypky3-L:1
- Stejný směr:28 [Flush]: Boční plech2:1 ↔ Plech násypky3-L:1
- Stejný směr:29 [Flush]: Plech násypky1:1 ↔ Plech násypky3-L:1
- Stejný směr:30 [Flush]: Plech násypky1:1 ↔ Plech násypky2-L:1
- Stejný směr:31 [Flush]: Plech násypky1:1 ↔ Plech násypky2-L:1
- Proti sobě:37 [Mate]: Základ2:1 ↔ Plech zadní:1
- Proti sobě:38 [Mate]: Boční plech2:1 ↔ Plech zadní:1
- Stejný směr:32 [Flush]: Boční plech2:1 ↔ Plech zadní:1
- Proti sobě:41 [Mate]: Základ2:1 ↔ Držák sloupu:1
- Úhel:1 [Angle]: Základ2:1 ↔ Držák sloupu:1
- Proti sobě:46 [Mate]: Držák sloupu:1 ↔ Úchyt sloupu2:1
- Stejný směr:33 [Flush]: Základ2:1 ↔ Boční plech2:1
- Stejný směr:34 [Flush]: Základ2:1 ↔ Plech přední:1
- Vložit:84 [Insert]: Rameno pravés:1 ↔ Přítlak5:1
- Vložit:85 [Insert]: Rameno pravés:1 ↔ Přítlak5:1
- Vložit:86 [Insert]: Rameno pravés:1 ↔ Deska střední:1
- Vložit:87 [Insert]: Rameno levés:1 ↔ Přítlak5:2
- Vložit:88 [Insert]: Rameno levés:1 ↔ Přítlak5:2
- Vložit:89 [Insert]: Rameno levés:1 ↔ Deska střední:1
- Stejný směr:35 [Flush]: Deska dolní:1 ↔ Deska střední:1
- Vložit:90 [Insert]: Držák desky:1 ↔ Přítlak5:1
- Vložit:91 [Insert]: Držák desky:1 ↔ Přítlak5:1
- Vložit:92 [Insert]: Držák desky:2 ↔ Přítlak5:2
- Vložit:93 [Insert]: Držák desky:2 ↔ Přítlak5:2
- Vložit:96 [Insert]: Přítlak3s:1 ↔ Ramano pravé:1
- Vložit:97 [Insert]: Přítlak3s:1 ↔ Ramano pravé:1
- Vložit:100 [Insert]: Přítlak3s:1 ↔ Vozík:2
- Vložit:101 [Insert]: Přítlak3s:1 ↔ Vozík:2
- Vložit:102 [Insert]: Deska dolní:1 ↔ Ramano pravé:1
- Vložit:103 [Insert]: Deska dolní:1 ↔ Ramano pravé:1
- Vložit:104 [Insert]: Přítlak4s:1 ↔ Ramano levé:1
- Vložit:105 [Insert]: Přítlak4s:1 ↔ Ramano levé:1
- Vložit:106 [Insert]: Přítlak4s:1 ↔ Vozík:1
- Vložit:107 [Insert]: Přítlak4s:1 ↔ Vozík:1
- Vložit:108 [Insert]: Deska dolní:1 ↔ Ramano levé:1
- Vložit:109 [Insert]: Deska dolní:1 ↔ Ramano levé:1
- Vložit:110 [Insert]: Držák dolní:1 ↔ Přítlak4s:1
- Vložit:111 [Insert]: Držák dolní:1 ↔ Přítlak4s:1
- Vložit:112 [Insert]: Držák dolní:2 ↔ Přítlak3s:1
- Vložit:113 [Insert]: Držák dolní:2 ↔ Přítlak3s:1
- Vložit:114 [Insert]: Přítlak1h:1 ↔ Vozík:3
- Vložit:115 [Insert]: Přítlak1h:1 ↔ Vozík:3
- Proti sobě:47 [Mate]: Přítlak1h:1 ↔ Deska1:1
- Vložit:117 [Insert]: Držák horní:1 ↔ Přítlak1h:1
- Vložit:118 [Insert]: Držák horní:1 ↔ Přítlak1h:1
- Vložit:119 [Insert]: Přítlak2h:1 ↔ Vozík:4
- Proti sobě:48 [Mate]: Přítlak2h:1 ↔ Vozík:4
- Vložit:122 [Insert]: Držák horní:3 ↔ Přítlak2h:1
- Vložit:123 [Insert]: Držák horní:3 ↔ Přítlak2h:1
- Vložit:124 [Insert]: CSN EN 24034 M10:2 ↔ Držák horní:3
- Vložit:125 [Insert]: CSN EN 24034 M10:3 ↔ Držák horní:3
- Úhel:2 [Angle]: Základ2:1 ↔ Dopravník vibrační3:1
- Úhel:3 [Angle]: Základ2:1 ↔ Dopravník vibrační3:1
- Stejný směr:36 [Flush]: Deska pevná:1 ↔ Dopravník vibrační3:1
- Proti sobě:50 [Mate]: Deska pevná:1 ↔ Dopravník vibrační3:1
- Proti sobě:51 [Mate]: Deska pevná:1 ↔ Dopravník vibrační3:1
- Proti sobě:62 [Mate]: Dopravník vibrační3:1 ↔ Skluzová dráha2:1
- Proti sobě:63 [Mate]: Plech násypky3:1 ↔ Skluzová dráha2:1
- Proti sobě:64 [Mate]: Skluzová dráha2:1 ↔ Držák dráhy:1
- Vložit:128 [Insert]: Držák dráhy:1 ↔ Držák dráhy2:1
- Proti sobě:67 [Mate]: Rám:1 ↔ Zadní plech krycí:1
- Stejný směr:39 [Flush]: Boční plech:1 ↔ Zadní plech krycí:1
- Proti sobě:68 [Mate]: Deska pevná:1 ↔ Zadní plech krycí:1
- Proti sobě:88 [Mate]: Dopravník vibrační3:1 ↔ Skluzová dráha2:1
- Proti sobě:89 [Mate]: Boční plech:1 ↔ Skluzová dráha2:1
- Vložit:133 [Insert]: Skluzová dráha2:1 ↔ Držák dráhy:1
- Vložit:134 [Insert]: Skluzová dráha2:1 ↔ Držák dráhy:1
- Vložit:138 [Insert]: Skluzová dráha2:1 ↔ CNS 4558 M4 x 16:1
- Vložit:139 [Insert]: Skluzová dráha2:1 ↔ CNS 4558 M4 x 16:2
- Proti sobě:91 [Mate]: Držák sloupu:1 ↔ DIN 125-2 A B 10,5:1
- Proti sobě:93 [Mate]: Držák sloupu:1 ↔ DIN 125-2 A B 10,5:2
- Proti sobě:95 [Mate]: Držák sloupu:1 ↔ DIN 125-2 A B 10,5:3
- Proti sobě:97 [Mate]: Držák sloupu:1 ↔ DIN 125-2 A B 10,5:4
- Proti sobě:99 [Mate]: DIN 125-2 A B 10,5:5 ↔ Úchyt sloupu2:2
- Proti sobě:101 [Mate]: DIN 125-2 A B 10,5:6 ↔ Úchyt sloupu2:2
- Proti sobě:103 [Mate]: DIN 125-2 A B 10,5:7 ↔ Úchyt sloupu2:1
- Proti sobě:105 [Mate]: DIN 125-2 A B 10,5:8 ↔ Úchyt sloupu2:1
- Vložit:140 [Insert]: DIN 125-2 A B 10,5:7 ↔ DIN 933 - nahrazený DIN EN 24017 M10  x 45:1
- Vložit:141 [Insert]: DIN 125-2 A B 10,5:1 ↔ DIN 933 - nahrazený DIN EN 24017 M10  x 45:2
- Proti sobě:123 [Mate]: Antivibrační noha:4 ↔ CSN EN 24034 M10:4
- Proti sobě:125 [Mate]: Antivibrační noha:2 ↔ CSN EN 24034 M10:5
- Proti sobě:127 [Mate]: Antivibrační noha:3 ↔ CSN EN 24034 M10:6
- Proti sobě:129 [Mate]: Antivibrační noha:1 ↔ CSN EN 24034 M10:7
- Proti sobě:131 [Mate]: CSN EN 24034 M10:4 ↔ DIN 125-2 A B 10,5:17
- Proti sobě:133 [Mate]: CSN EN 24034 M10:5 ↔ DIN 125-2 A B 10,5:18
- Proti sobě:135 [Mate]: CSN EN 24034 M10:6 ↔ DIN 125-2 A B 10,5:19
- Proti sobě:137 [Mate]: CSN EN 24034 M10:7 ↔ DIN 125-2 A B 10,5:20
- Vložit:142 [Insert]: Základ2:1 ↔ DIN 125-2 A B 10,5:20
- Vložit:143 [Insert]: Základ2:1 ↔ DIN 125-2 A B 10,5:17
- Vložit:144 [Insert]: Základ2:1 ↔ DIN 125-2 A B 10,5:18
- Vložit:145 [Insert]: Základ2:1 ↔ DIN 125-2 A B 10,5:19
- Proti sobě:139 [Mate]: Boční plech:1 ↔ Šroub do plechu s vroubkovanou šestihrannou hlavou s drážkou a podložkou - Typ BP - Palcový 1/4-14 - 0,75:1
- Proti sobě:141 [Mate]: Boční plech:1 ↔ Šroub do plechu s vroubkovanou šestihrannou hlavou s drážkou a podložkou - Typ BP - Palcový 1/4-14 - 0,75:4
- Proti sobě:146 [Mate]: Dopravník vibrační3:1 ↔ Matice upínací:1
- Proti sobě:147 [Mate]: Dopravník vibrační3:1 ↔ Matice upínací:1
- Proti sobě:148 [Mate]: Dopravník vibrační3:1 ↔ Matice upínací:2
- Proti sobě:149 [Mate]: Dopravník vibrační3:1 ↔ Matice upínací:2
- Stejný směr:40 [Flush]: Dopravník vibrační3:1 ↔ Matice upínací:1
- Proti sobě:150 [Mate]: Dopravník vibrační3:1 ↔ Matice upínací:2
- Proti sobě:151 [Mate]: Dopravník vibrační3:1 ↔ Matice upínací:13
- Proti sobě:152 [Mate]: Dopravník vibrační3:1 ↔ Matice upínací:13
- Proti sobě:153 [Mate]: Dopravník vibrační3:1 ↔ Matice upínací:13
- Proti sobě:155 [Mate]: Dopravník vibrační3:1 ↔ DIN 125-1 A A 6,4:1
- Proti sobě:157 [Mate]: Dopravník vibrační3:1 ↔ DIN 125-1 A A 6,4:2
- Proti sobě:159 [Mate]: Dopravník vibrační3:1 ↔ DIN 125-1 A A 6,4:3
- Proti sobě:161 [Mate]: Dopravník vibrační3:1 ↔ DIN 125-1 A A 6,4:5
- Vložit:152 [Insert]: DIN 933 - nahrazený DIN EN 24017 M6  x 45:1 ↔ DIN 125-1 A A 6,4:4
- Vložit:153 [Insert]: DIN 933 - nahrazený DIN EN 24017 M6  x 45:2 ↔ DIN 125-1 A A 6,4:5
- Vložit:154 [Insert]: DIN 125-1 A A 6,4:1 ↔ DIN 933 - nahrazený DIN EN 24017 M6  x 35:3
- Vložit:155 [Insert]: DIN 933 - nahrazený DIN EN 24017 M6  x 35:2 ↔ DIN 125-1 A A 6,4:3
- Vložit:156 [Insert]: DIN 933 - nahrazený DIN EN 24017 M6  x 35:1 ↔ DIN 125-1 A A 6,4:6
- Proti sobě:163 [Mate]: Boční plech:1 ↔ Šroub do plechu s normální vroubkovanou šestihrannou hlavou - Typ BP - Palcový 1/4-14 - 0,75:1
- Proti sobě:165 [Mate]: Plech násypky3-L:1 ↔ DIN 125-1 A A 6,4:18
- Proti sobě:167 [Mate]: Plech násypky3:1 ↔ DIN 125-1 A A 6,4:20
- Vložit:162 [Insert]: DIN 125-1 A A 6,4:18 ↔ DIN 933 - nahrazený DIN EN 24017 M6  x 16:1
- Proti sobě:169 [Mate]: CSN EN 24034 M6:1 ↔ DIN 125-1 A A 6,4:24
- Proti sobě:171 [Mate]: CSN EN 24034 M6:2 ↔ DIN 125-1 A A 6,4:25
- Proti sobě:173 [Mate]: CSN EN 24034 M6:3 ↔ DIN 125-1 A A 6,4:22
- Proti sobě:175 [Mate]: CSN EN 24034 M6:4 ↔ DIN 125-1 A A 6,4:23
- Stejný směr:41 [Flush]: Boční plech2:1
- Vložit:176 [Insert]: Dopravník vibrační3:1 ↔ DIN 7991 M4x10:1
- Vložit:180 [Insert]: Přítlak2h:1 ↔ Deska1:1
- Úhel:12 [Angle]: Deska střední:1 ↔ Deska1:1
- Stejný směr:42 [Flush]: Základ2:1 ↔ Držák sloupu:1
- Proti sobě:180 [Mate]: Držák sloupu:1 ↔ Úchyt sloupu2:2
- Stejný směr:44 [Flush]: Držák sloupu:1 ↔ Úchyt sloupu2:2
- Vložit:181 [Insert]: Dopravník vibrační3:1 ↔ Základová deska3:1
- Vložit:183 [Insert]: Základová deska3:1 ↔ Příruba:1
- Vložit:184 [Insert]: Základová deska3:1 ↔ Příruba:1
- Vložit:185 [Insert]: Příruba:1 ↔ Nosný sloup:1
- Proti sobě:182 [Mate]: Držák dráhy2:1 ↔ Držák tyče:1
- Úhel:13 [Angle]: Základová deska3:1 ↔ Držák tyče:1
- Proti sobě:187 [Mate]: Základová deska3:1 ↔ Držák tyče:2
- Proti sobě:189 [Mate]: Držák tyče:1 ↔ Držák tyče:2
- Proti sobě:190 [Mate]: Držák tyče:2 ↔ Tyč válce:1
- Proti sobě:191 [Mate]: Tyč válce:1 ↔ Držák elektromagnetu:1
- Proti sobě:192 [Mate]: Tyč válce:1 ↔ Držák elektromagnetu:1
- Proti sobě:193 [Mate]: Tyč válce:1 ↔ Držák elektromagnetu:1
- Úhel:14 [Angle]: Dopravník vibrační3:1 ↔ Držák elektromagnetu:1
- Proti sobě:194 [Mate]: Dopravník vibrační3:1 ↔ Držák elektromagnetu:1
- Vložit:187 [Insert]: Tyčka elektromotoru:1 ↔ Zarážka:1
- Úhel:15 [Angle]: Elektromagnet:1 ↔ Zarážka:1
- Proti sobě:195 [Mate]: Dopravník vibrační3:1 ↔ Elektromagnet:1
- Úhel:16 [Angle]: Elektromagnet:1 ↔ Držák elektromagnetu:1
- Vložit:188 [Insert]: Elektromagnet:1 ↔ Držák elektromagnetu2:1
- Proti sobě:196 [Mate]: Držák elektromagnetu:1 ↔ Držák elektromagnetu2:1
- Proti sobě:197 [Mate]: Elektromagnet:1 ↔ Tyčka elektromotoru:1
- Proti sobě:199 [Mate]: Zarážka:1 ↔ DIN 125-1 A A 6,4:31
- Proti sobě:201 [Mate]: DIN 125-1 A A 6,4:31 ↔ CSN EN 24034 M6:5
- Proti sobě:202 [Mate]: Držák elektromagnetu2:1 ↔ DIN 125-1 A A 6,4:32
- Proti sobě:203 [Mate]: Držák elektromagnetu2:1 ↔ DIN 125-1 A A 6,4:33
- Proti sobě:205 [Mate]: Držák elektromagnetu:1 ↔ DIN 125-1 A A 6,4:34
- Proti sobě:207 [Mate]: Držák elektromagnetu:1 ↔ DIN 125-1 A A 6,4:35
- Vložit:191 [Insert]: DIN 125-1 A A 6,4:33 ↔ DIN 933 - nahrazený DIN EN 24017 M6  x 25:2
- Vložit:192 [Insert]: DIN 125-1 A A 6,4:32 ↔ DIN 933 - nahrazený DIN EN 24017 M6  x 25:1
- Proti sobě:208 [Mate]: CSN EN 24034 M6:6 ↔ DIN 933 - nahrazený DIN EN 24017 M6  x 25:1
- Proti sobě:209 [Mate]: CSN EN 24034 M6:7 ↔ DIN 933 - nahrazený DIN EN 24017 M6  x 25:2
- Stejný směr:45 [Flush]: Držák elektromagnetu:1 ↔ Držák elektromagnetu2:1
- Proti sobě:214 [Mate]: Dopravník vibrační3:1 ↔ DIN 125-1 A A 6,4:36
- Proti sobě:215 [Mate]: Dopravník vibrační3:1 ↔ DIN 125-1 A A 6,4:36
- Úhel:19 [Angle]: Dopravník vibrační3:1 ↔ DIN 933 - nahrazený DIN EN 24017 M6  x 6:7
- Proti sobě:216 [Mate]: Dopravník vibrační3:1 ↔ DIN 125-1 A A 6,4:36
- Úhel:21 [Angle]: Držák elektromagnetu2:1 ↔ Držák senzoru2:1
- Vložit:198 [Insert]: Senzor:1 ↔ Držák senzoru2:1
- Vložit:199 [Insert]: Senzor:2 ↔ Držák senzoru2:1
- Úhel:22 [Angle]: Základ2:1 ↔ Základová deska3:1
- Proti sobě:217 [Mate]: Držák elektromagnetu2:1 ↔ Držák senzoru2:1
- Vložit:200 [Insert]: Držák elektromagnetu2:1 ↔ Držák senzoru2:1
- Proti sobě:218 [Mate]: Základová deska3:1 ↔ Držák tyče:3
- Stejný směr:46 [Flush]: Držák tyče:2 ↔ Držák tyče:3
- Stejný směr:47 [Flush]: Držák tyče:2 ↔ Držák tyče:3
- Proti sobě:219 [Mate]: Držák tyče:3 ↔ Tyč válce:2
- Proti sobě:220 [Mate]: Tyč válce:2 ↔ Držák senzoru3:1
- Proti sobě:221 [Mate]: Tyč válce:2 ↔ Držák senzoru3:1
- Proti sobě:222 [Mate]: Držák senzoru3:1 ↔ Držák senzoru2:2
- Vložit:201 [Insert]: Držák senzoru3:1 ↔ Držák senzoru2:2
- Proti sobě:223 [Mate]: Základová deska3:1 ↔ Držák tyče:2
- Proti sobě:224 [Mate]: Základová deska3:1 ↔ Držák tyče:1
- Vložit:202 [Insert]: DIN 125-1 A A 6,4:37 ↔ Držák senzoru2:1
- Proti sobě:225 [Mate]: DIN 125-1 A A 6,4:38 ↔ Držák senzoru2:1
- Vložit:203 [Insert]: Držák elektromagnetu2:1 ↔ DIN 125-1 A A 6,4:39
- Vložit:204 [Insert]: Držák elektromagnetu2:1 ↔ DIN 125-1 A A 6,4:40
- Vložit:205 [Insert]: DIN 125-1 A A 6,4:40 ↔ CSN EN 24034 M6:9
- Vložit:206 [Insert]: DIN 125-1 A A 6,4:39 ↔ CSN EN 24034 M6:8
- Vložit:207 [Insert]: DIN 125-1 A A 6,4:37 ↔ DIN 933 - nahrazený DIN EN 24017 M6  x 20:1
- Vložit:208 [Insert]: DIN 125-1 A A 6,4:38 ↔ DIN 933 - nahrazený DIN EN 24017 M6  x 20:2
- Proti sobě:226 [Mate]: CSN EN 24034 M6:9 ↔ DIN 933 - nahrazený DIN EN 24017 M6  x 20:2
- Vložit:209 [Insert]: DIN 125-1 A A 6,4:44 ↔ Držák senzoru2:2
- Vložit:210 [Insert]: Držák senzoru3:1 ↔ DIN 125-1 A A 6,4:43
- Vložit:211 [Insert]: Držák senzoru3:1 ↔ DIN 125-1 A A 6,4:42
- Proti sobě:227 [Mate]: DIN 125-1 A A 6,4:41 ↔ Držák senzoru2:2
- Vložit:212 [Insert]: CSN EN 24034 M6:11 ↔ DIN 125-1 A A 6,4:43
- Vložit:213 [Insert]: CSN EN 24034 M6:10 ↔ DIN 125-1 A A 6,4:42
- Vložit:214 [Insert]: DIN 933 - nahrazený DIN EN 24017 M6  x 25:4 ↔ DIN 125-1 A A 6,4:44
- Vložit:215 [Insert]: DIN 933 - nahrazený DIN EN 24017 M6  x 25:3 ↔ DIN 125-1 A A 6,4:41
- Proti sobě:228 [Mate]: DIN 933 - nahrazený DIN EN 24017 M6  x 25:3 ↔ CSN EN 24034 M6:10
- Vložit:216 [Insert]: Držák senzoru2:1 ↔ DIN EN 24035 M18:1
- Vložit:217 [Insert]: Držák senzoru2:1 ↔ DIN EN 24035 M18:2
- Vložit:218 [Insert]: Držák senzoru2:1 ↔ DIN EN 24035 M18:4
- Vložit:219 [Insert]: Držák senzoru2:1 ↔ DIN EN 24035 M18:3
- Proti sobě:230 [Mate]: Základ2:1 ↔ DIN 125-1 A A 10,5:1
- Proti sobě:232 [Mate]: Základ2:1 ↔ DIN 125-1 A A 10,5:2
- Proti sobě:234 [Mate]: Základ2:1 ↔ DIN 125-1 A A 10,5:3
- Proti sobě:236 [Mate]: Základ2:1 ↔ DIN 125-1 A A 10,5:4
- Proti sobě:238 [Mate]: Základ2:1 ↔ DIN 125-1 A A 10,5:5
- Proti sobě:240 [Mate]: Základ2:1 ↔ DIN 125-1 A A 10,5:6
- Proti sobě:242 [Mate]: Základ2:1 ↔ DIN 125-1 A A 10,5:7
- Proti sobě:244 [Mate]: Základ2:1 ↔ DIN 125-1 A A 10,5:8
- Proti sobě:246 [Mate]: Základ2:1 ↔ DIN 125-1 A A 10,5:9
- Proti sobě:248 [Mate]: Základ2:1 ↔ DIN 125-1 A A 10,5:10
- Proti sobě:250 [Mate]: Základ2:1 ↔ DIN 125-1 A A 10,5:11
- Proti sobě:252 [Mate]: Základ2:1 ↔ DIN 125-1 A A 10,5:12
- Proti sobě:254 [Mate]: DIN 125-1 A A 10,5:9 ↔ CSN EN 24034 M10:8
- Proti sobě:256 [Mate]: DIN 125-1 A A 10,5:11 ↔ CSN EN 24034 M10:10
- Proti sobě:258 [Mate]: DIN 125-1 A A 10,5:12 ↔ CSN EN 24034 M10:11
- Proti sobě:260 [Mate]: Držák tyče:1 ↔ CNS 3932 M 6 x 10:1
- Proti sobě:262 [Mate]: Držák tyče:2 ↔ CNS 3932 M 6 x 10:2
- Proti sobě:264 [Mate]: Držák tyče:3 ↔ CNS 3932 M 6 x 10:3
- Vložit:221 [Insert]: Boční plech2:1 ↔ Šroub do plechu s vroubkovanou šestihrannou hlavou s drážkou a podložkou - Typ BP - Palcový 1/4-14 - 0,75:10
- Proti sobě:266 [Mate]: Boční plech2:1 ↔ Šroub do plechu s vroubkovanou šestihrannou hlavou s drážkou a podložkou - Typ BP - Palcový 1/4-14 - 0,75:27
- Proti sobě:268 [Mate]: Příruba:1 ↔ DIN 125-1 A A 10,5:13
- Proti sobě:270 [Mate]: DIN 933 - nahrazený DIN EN 24017 M10  x 8:1 ↔ DIN 125-1 A A 10,5:16
- Proti sobě:272 [Mate]: Držák dráhy:1 ↔ DIN 125-1 A A 15:1
- Proti sobě:274 [Mate]: Držák dráhy:1 ↔ DIN 125-1 A A 15:2
- Vložit:222 [Insert]: DIN 125-1 A A 15:2 ↔ CSN EN 24034 M14:1
- Vložit:223 [Insert]: DIN 125-1 A A 15:1 ↔ DIN 933 - nahrazený DIN EN 24017 M14  x 35:1
- Proti sobě:276 [Mate]: Držák dráhy:1 ↔ DIN 125-1 A A 4,3:4
- Proti sobě:278 [Mate]: Držák dráhy:1 ↔ DIN 125-1 A A 4,3:5
- Proti sobě:280 [Mate]: DIN 125-1 A A 4,3:5 ↔ CSN EN 24034 M5:1
- Proti sobě:282 [Mate]: DIN 125-1 A A 4,3:4 ↔ CSN EN 24034 M5:2
- Proti sobě:284 [Mate]: Držák tyče:3 ↔ DIN 125-1 A A 6,4:50
- Vložit:235 [Insert]: Dopravník vibrační3:1 ↔ CNS 4558 M4 x 10:1
- Proti sobě:286 [Mate]: Výztuha rohu-P:1 ↔ DIN 125-1 A A 8,4:6
- Vložit:251 [Insert]: DIN 125-1 A A 8,4:7 ↔ DIN 933 - nahrazený DIN EN 24017 M8  x 25:1
- Vložit:252 [Insert]: DIN 125-1 A A 8,4:8 ↔ DIN 933 - nahrazený DIN EN 24017 M8  x 25:2
- Vložit:261 [Insert]: Nosný sloup:1 ↔ Zátka sloupu:1
- Proti sobě:289 [Mate]: DIN 933 - nahrazený DIN EN 24017 M12  x 30:1 ↔ Zátka sloupu:1
- Proti sobě:290 [Mate]: Základ2:1 ↔ DIN 933 - nahrazený DIN EN 24017 M12  x 30:1
- Proti sobě:291 [Mate]: Držák sloupu:1 ↔ Nosný sloup:1
- Proti sobě:293 [Mate]: DIN 125-1 A A 6,4:56 ↔ DIN 933 - nahrazený DIN EN 24017 M6  x 6:16
